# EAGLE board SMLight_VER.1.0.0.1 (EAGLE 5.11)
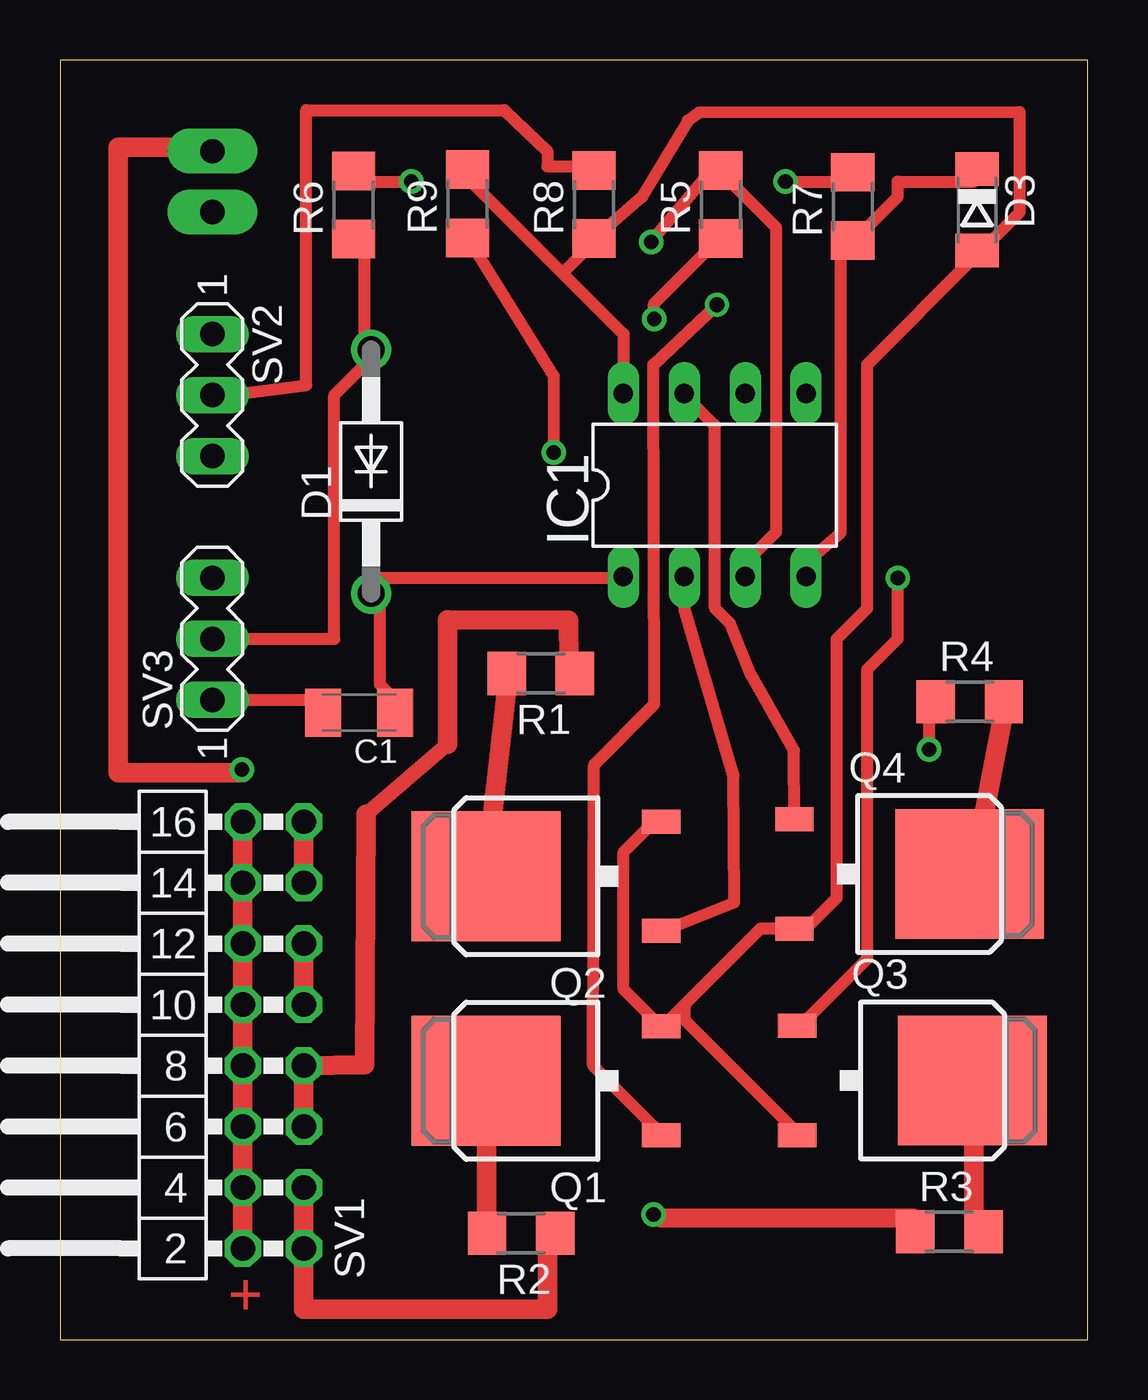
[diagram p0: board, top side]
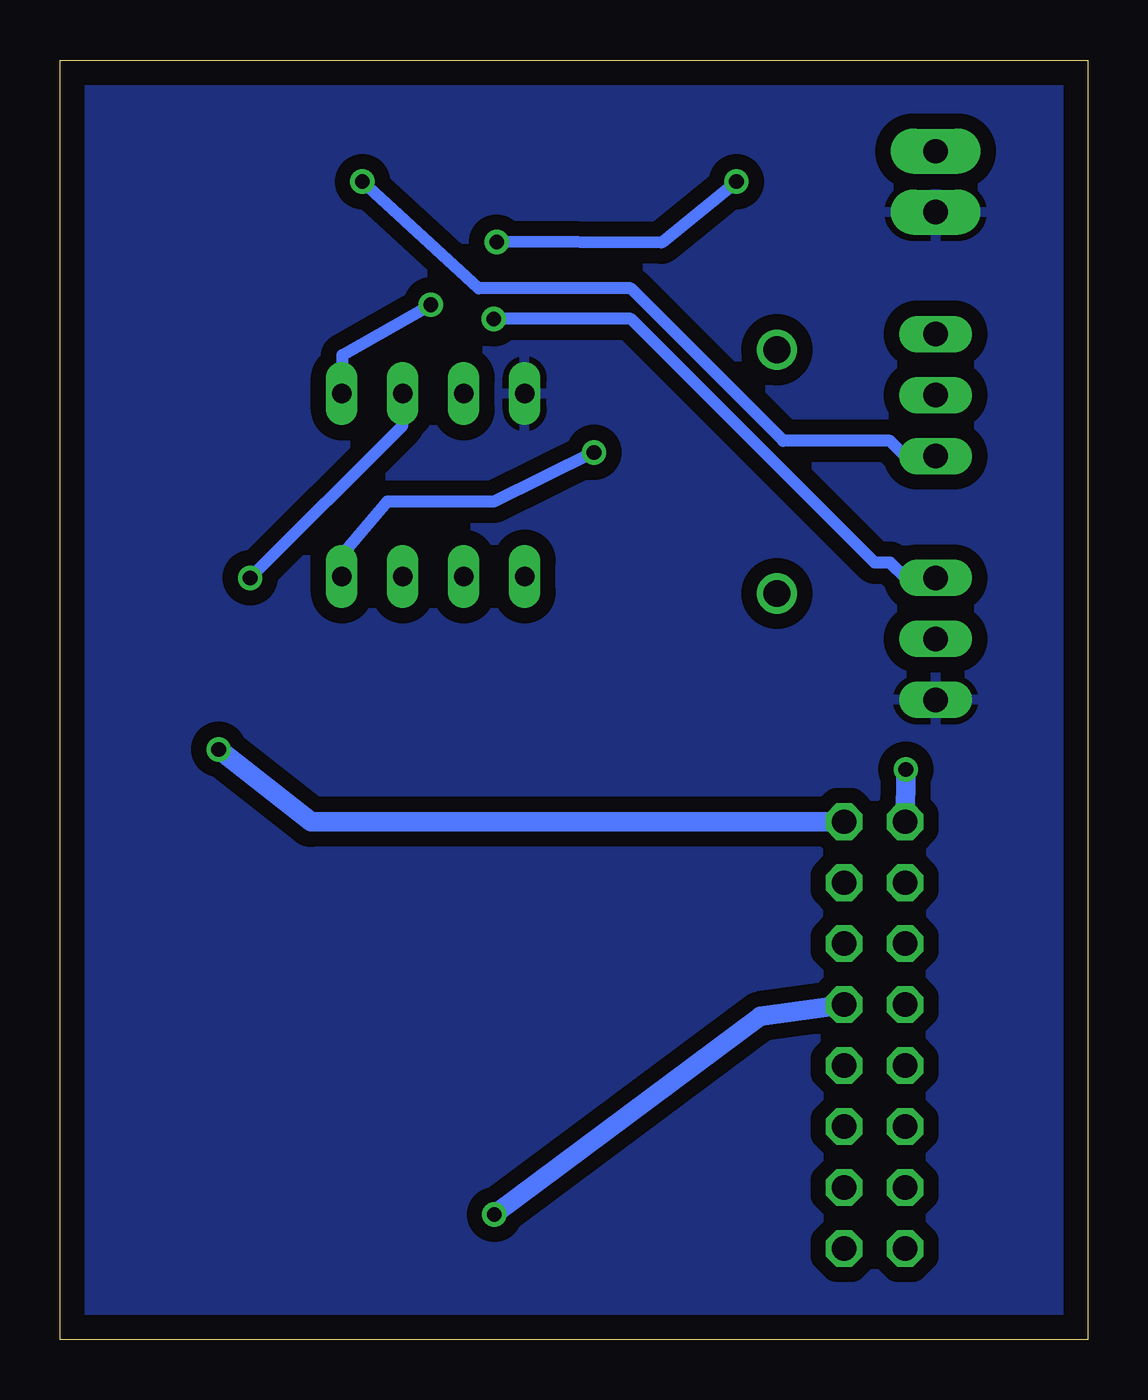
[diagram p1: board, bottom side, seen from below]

Size 42.85 x 53.33 mm. Coordinates in mm from the lower left corner, seen from the top.
Outline: 0,0 42.85,0 42.85,53.33 0,53.33 0,0
Copper layers (1*16): Top 0.035mm / dielectric 1.5mm / Bottom 0.035mm
Design rules "default": minimum track width 10mil, minimum drill 24mil, track to track 8mil, track to pad 8mil, pad to pad 8mil, via to via 8mil, smd to smd 8mil, copper to edge 40mil, drill to drill 8mil, minimum pad ring 10mil, minimum via ring 8mil, stop-mask expansion 4mil, vias tented up to drill 0mil, thermal gap 10mil
Net classes: 0 default: width 0.508 mm, clearance 0.635 mm; 1 VCC: width 0.635 mm, clearance 0.305 mm; 2 LED: width 0.635 mm, clearance 0.305 mm

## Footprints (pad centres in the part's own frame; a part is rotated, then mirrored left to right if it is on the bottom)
C1206K = smd 1.5 x 2: 1 -1.5,0; 2 1.5,0
DO41-10 = drill 1.118 round: A 5.08,0; C -5.08,0
SOD80C = smd 1.4 x 1.8: A 1.7,0; C -1.7,0
DIL8 = drill 0.813 long: 1 -3.81,-3.81; 2 -1.27,-3.81; 3 1.27,-3.81; 4 3.81,-3.81; 5 3.81,3.81; 6 1.27,3.81; 7 -1.27,3.81; 8 -3.81,3.81
1X02_LONGPADS = drill 1.016 pad 1.88 long: 1 0,0; 2 2.54,0
D-PAK_TO252AA = smd 1 x 1.6: 1 -2.28,-4.8; 3 2.28,-4.8 | smd 5.4 x 6.2: 4 0,2.5
R1206 = smd 1.6 x 1.803: 1 -1.422,0; 2 1.422,0
MA08-2W = drill 1.016 octagon: 1 -8.89,-1.27; 2 -8.89,1.27; 3 -6.35,-1.27; 4 -6.35,1.27; 5 -3.81,-1.27; 6 -3.81,1.27; 7 -1.27,-1.27; 8 -1.27,1.27; 9 1.27,-1.27; 10 1.27,1.27; 11 3.81,-1.27; 12 3.81,1.27; 13 6.35,-1.27; 14 6.35,1.27; 15 8.89,-1.27; 16 8.89,1.27
MA03-1 = drill 1.016 long: 1 -2.54,0; 2 0,0; 3 2.54,0

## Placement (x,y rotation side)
C1  100NF  [C1206K]  12.47,26.14 180 top
D1  1N4004  [DO41-10]  12.97,36.18 90 top
D3  5.1V  [SOD80C]  38.23,47.09 270 top
IC1  PIC12F683P  [DIL8]  27.29,35.62 0 top
JP1  [1X02_LONGPADS]  6.35,46.99 90 top
Q1  IRF1205  [D-PAK_TO252AA]  20.26,10.8 90 top
Q2  IRF1205  [D-PAK_TO252AA]  20.26,19.32 90 top
Q3  IRF1205  [D-PAK_TO252AA]  35.54,10.81 270 top
Q4  IRF1205  [D-PAK_TO252AA]  35.41,19.41 270 top
R1  470R  [R1206]  20.04,27.77 180 top
R2  470R  [R1206]  19.22,4.44 180 top
R3  470R  [R1206]  37.08,4.5 0 top
R4  470R  [R1206]  37.92,26.59 0 top
R5  680R  [R1206]  27.54,47.31 90 top
R6  8.2K  [R1206]  12.24,47.29 90 top
R7  1.2K  [R1206]  33.04,47.23 90 top
R8  680R  [R1206]  22.26,47.31 90 top
R9  8.2K  [R1206]  16.99,47.34 90 top
SV1  [MA08-2W]  8.89,12.7 90 top
SV2  [MA03-1]  6.35,39.37 270 top
SV3  [MA03-1]  6.35,29.21 90 top

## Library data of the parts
C1 R1-R9 = rcl
D1 D3 = diode
IC1 = microchip; MF: MICROCHIP; MPN: PIC12F683-I/P; OC_FARNELL: 9759034; OC_NEWARK: 89H0442
JP1 = SparkFun
Q1-Q4 = transistor-power
SV1-SV3 = con-lstb; OC_FARNELL: unknown; OC_NEWARK: unknown

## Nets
GND: C1.2 D3.A IC1.8 JP1.1 Q1.3 Q2.3 Q3.3 Q4.3 R8.1 R9.2 SV3.1
N$1: C1.1 D1.C IC1.1
N$2: IC1.3 R5.2 R6.2
N$3 [LED]: R4.1 SV1.13 SV1.15
N$4: R3.1 SV1.9 SV1.11
N$5: R2.1 SV1.1 SV1.3
N$6: R1.1 SV1.5 SV1.7
N$7: Q3.4 R3.2
N$8: Q4.4 R4.2
N$9: Q1.4 R2.2
N$10: Q2.4 R1.2
N$11: R5.1 SV3.3
N$12: D1.A R6.1 SV3.2
N$13: D3.C IC1.4 R7.1 R9.1
N$14: IC1.2 Q2.1
N$15: IC1.7 Q4.1
N$16: IC1.6 Q3.1
N$17: IC1.5 Q1.1
N$20: R7.2 SV2.3
N$21: R8.2 SV2.2
S$4: SV1.16

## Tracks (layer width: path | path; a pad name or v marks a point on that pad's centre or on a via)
GND
  Top 0.508: 20.95,44.45 23.5,41.91 23.5,40.01 IC1.8 | 20.95,44.45 17.14,48.26 R9.2 | 20.95,44.45 22.23,45.72 R8.1 24.26,47.63 26.17,50.8 26.64,51.14 40.01,51.16 40.01,46.99 38.73,45.72 D3.A 38.1,45.09 33.66,40.64 33.66,30.48 32.38,29.21 32.38,18.41 31.11,17.14 Q4.3 30.48,17.14 29.21,17.14 26.04,13.97 | SV3.1 10.79,26.67 C1.2 | 26.04,13.97 25.4,13.34 Q1.3 24.77,13.34 23.5,14.61 23.5,20.32 24.77,21.59 Q2.3 | 26.04,13.97 26.04,13.34 30.48,8.89 Q3.3
  pour Bottom: 0,0 0,53.34 43.18,53.34 43.18,0
N$1
  Top 0.508: C1.1 13.97,26.67 13.34,27.3 13.34,30.48 D1.C 13.34,31.11 13.34,31.75 22.86,31.75 IC1.1
N$2  (via drill 0.61)
  Top 0.508: v14.65,48.26 12.7,48.26 R6.2 | v24.64,45.75 27.3,48.9 R5.2 27.94,48.26 29.84,46.35 29.84,33.66 28.57,32.38 IC1.3
  Bottom 0.508: v14.65,48.26 17.78,45.72 v24.64,45.75
N$3  (via drill 0.61)
  Top 0.508: v36.23,24.6 36.23,26.51 R4.1
  Top 0.813: SV1.13 SV1.15
  Bottom 0.813: v36.23,24.6 32.38,21.59 SV1.15
N$4  (via drill 0.61)
  Top 0.508: v24.74,5.23 25.05,5.08 | 35.56,5.08 R3.1
  Top 0.813: 25.05,5.08 35.56,5.08 | SV1.9 SV1.11
  Bottom 0.813: v24.74,5.23 13.66,13.48 SV1.9
N$5
  Top 0.508: 20.32,3.81 R2.1
  Top 0.813: 20.32,3.81 20.32,1.27 10.16,1.27 SV1.1 SV1.3
N$6
  Top 0.508: 21.22,28.23 R1.1
  Top 0.61: 12.77,21.9 16.16,24.82
  Top 0.813: 21.22,28.23 21.2,29.98 16.16,30.01 16.16,24.82 | 12.77,21.9 12.7,11.47 SV1.7 SV1.5
N$7
  Top 0.508: R3.2 38.1,5.08 | 38.1,10.79 Q3.4
  Top 0.813: 38.1,5.08 38.1,10.79
N$8
  Top 0.508: 39.41,26.51 R4.2 | Q4.4 38.1,19.68
  Top 0.813: 38.1,19.68 39.41,26.51
N$9
  Top 0.508: R2.2 17.78,4.45 | 17.78,10.79 Q1.4
  Top 0.813: 17.78,4.45 17.78,10.79
N$10
  Top 0.508: 18.68,27.6 R1.2 | Q2.4 17.78,19.68
  Top 0.813: 17.78,19.68 18.68,27.6
N$11  (via drill 0.61)
  Top 0.508: v24.77,42.55 24.77,43.18 27.3,45.72 R5.1
  Bottom 0.508: v24.77,42.55 19.05,42.55 8.89,32.38 8.26,32.38 7.62,31.75 SV3.3
N$12
  Top 0.508: R6.1 12.7,45.72 12.7,41.27 D1.A 12.7,40.64 11.43,39.37 11.43,29.21 SV3.2
N$13  (via drill 0.61)
  Top 0.508: D3.C 38.1,48.26 34.92,48.26 34.92,47.62 33.66,46.35 R7.1 33.02,45.72 32.55,45.07 32.55,33.64 31.11,32.38 IC1.4 | v20.59,36.98 20.59,40.16 17.14,45.72 R9.1
  Bottom 0.508: v20.59,36.98 24.77,34.92 29.21,34.92 31.2,32.6 31.2,31.87 31.11,31.75 IC1.4
N$14
  Top 0.508: Q2.1 25.4,17.14 28.11,18.23 28.08,23.52 26.04,30.48 26.04,31.75 IC1.2
N$15
  Top 0.508: Q4.1 30.6,24.56 28.8,27.72 27.94,29.84 27.3,30.48 27.3,38.1 26.04,39.37 IC1.7
N$16  (via drill 0.61)
  Top 0.508: v34.92,31.75 34.92,29.21 33.66,27.94 33.66,15.88 31.11,13.34 Q3.1
  Bottom 0.508: v34.92,31.75 28.57,38.1 28.57,39.37 IC1.6
N$17  (via drill 0.61)
  Top 0.508: v27.39,43.13 24.73,40.64 24.78,26.49 22.27,23.95 22.23,11.43 24.77,8.89 Q1.1
  Bottom 0.508: v27.39,43.13 31.09,41.03 31.09,40.4 31.11,39.37 IC1.5
N$20  (via drill 0.61)
  Top 0.508: v30.24,48.26 33.02,48.26 R7.2
  Bottom 0.508: v30.24,48.26 25.4,43.81 19.05,43.81 12.7,37.47 8.26,37.47 7.62,36.83 SV2.3
N$21
  Top 0.508: SV2.2 6.99,39.37 10.27,39.78 10.27,51.24 18.52,51.24 20.32,49.53 20.32,48.9 22.23,48.9 R8.2
S$1
  Top 0.813: 7.61,23.64 2.42,23.64 2.42,49.7 6.48,49.7
S$2
  Top 0.61: 7.65,21.54 7.67,21.54
S$3
  Top 0.813: 7.65,3.74 7.61,3.74 7.61,21.63
S$4  (via drill 0.61)
  Bottom 0.813: SV1.16 v7.59,23.77
S$11
  Top 0.61: 7.65,13.9 7.62,13.93

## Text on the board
Top: +
tOrigins: + | 12V | _ | NC | RS232 | GND | TX | S | REC | + | GND | LED 12V | _ | +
